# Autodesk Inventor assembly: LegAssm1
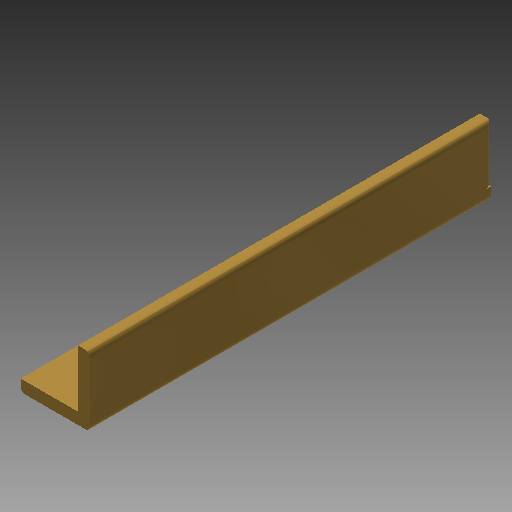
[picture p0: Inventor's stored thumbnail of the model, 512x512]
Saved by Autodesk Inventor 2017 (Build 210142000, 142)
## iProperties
Created: 2017-05
Part Number: LegAssm1
Document SubType Name: Assembly
Designer: John
Author: John
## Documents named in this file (5)
- D:\3D Printer Designs\John Ledden Designs\Infinity Mirror Table\SavanDrawings\LegAssm1.iam
- D:\3D Printer Designs\John Ledden Designs\Infinity Mirror Table\SavanDrawings\Leg1.ipt
- D:\3D Printer Designs\John Ledden Designs\Infinity Mirror Table\SavanDrawings\Leg2.ipt
- D:\3D Printer Designs\John Ledden Designs\Infinity Mirror Table\SavanDrawings\CornerShelfBracket.ipt
- D:\3D Printer Designs\John Ledden Designs\Infinity Mirror Table\SavanDrawings\8_Screw_-5inch.ipt
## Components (16 placed, 16 different names)
1. Leg1_1001
2. Leg2_1002
3. CornerShelfBracket_1003
4. CornerShelfBracket_1004
5. 8_Screw_-5inch_1005
6. 8_Screw_-5inch_1006
7. 8_Screw_-5inch_1007
8. 8_Screw_-5inch_1008
9. 8_Screw_-5inch_1009
10. 8_Screw_-5inch_1010
11. 8_Screw_-5inch_1011
12. 8_Screw_-5inch_1012
13. 8_Screw_-5inch_1013
14. 8_Screw_-5inch_1014
15. 8_Screw_-5inch_1015
16. 8_Screw_-5inch_1016
